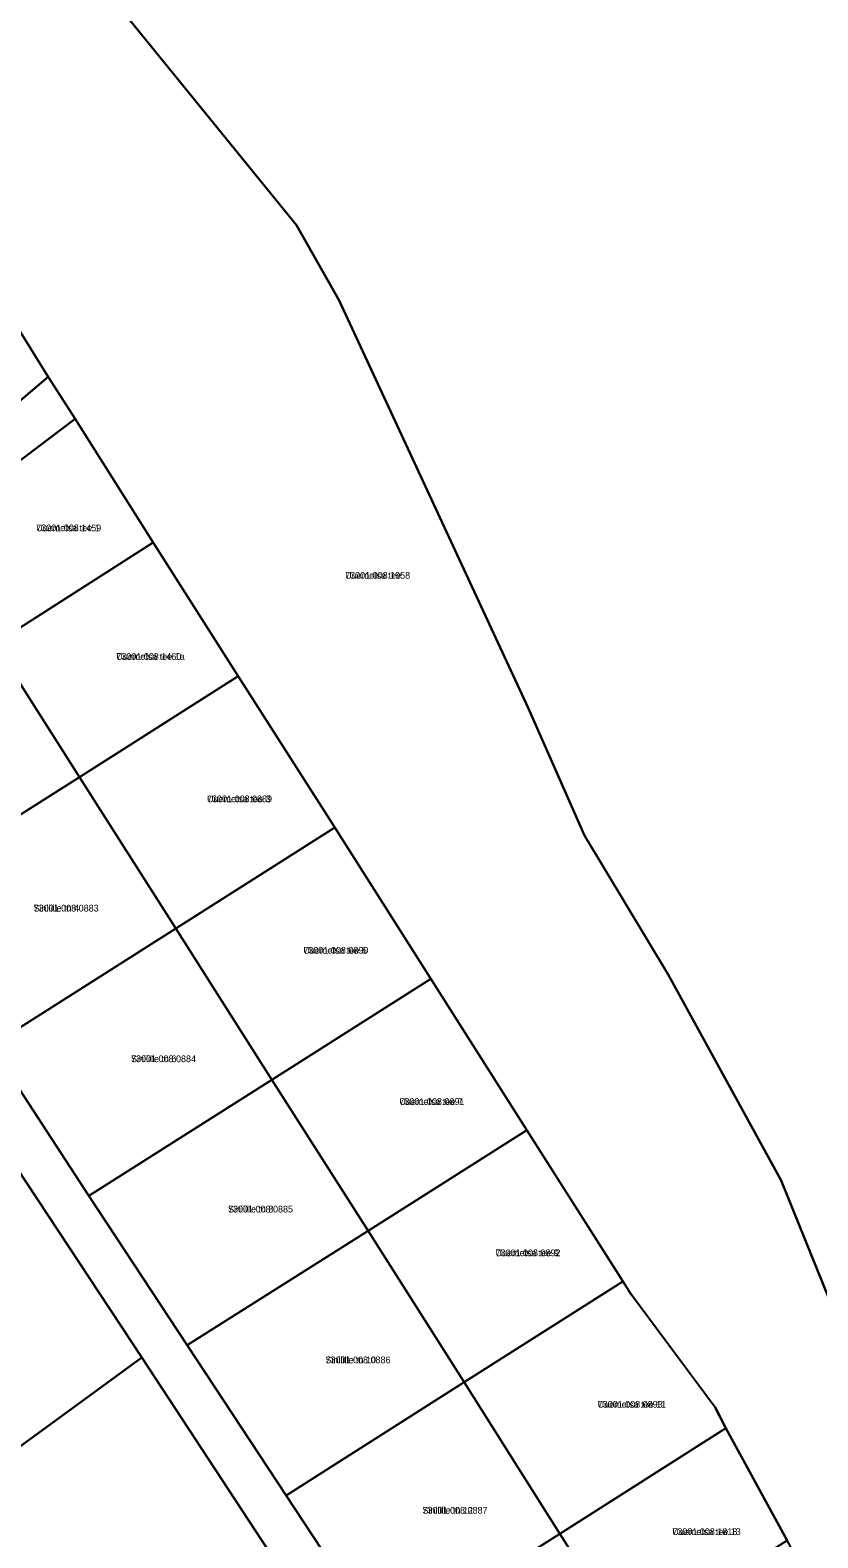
# Model space of a CAD drawing. Extents: x 524000 to 564260, y 6469338 to 6496391.
# Drawn here: x 533524.2 to 533700, y 6469655.2 to 6469991.7 of the extents above; entities that cross this region are included whole.
import ezdxf

# ---------------------------------------------------------------- set-up
doc = ezdxf.new("R2010")
doc.units = 0
for name, color, linetype in [('L_AADRESS', 7, 'Continuous'), ('PIIR', 7, 'Continuous'), ('TUNNUS', 7, 'Continuous')]:
    doc.layers.add(name, color=color, linetype=linetype)

msp = doc.modelspace()

# ---------------------------------------------------------------- linework, layer by layer
at = {"layer": 'PIIR'}
for points in [[(533707.29, 6469629.03), (533693.17, 6469654.63), (533679.45, 6469679.69), (533677.05, 6469684.35), (533658.36, 6469709.54), (533656.52, 6469712.46), (533635.06, 6469746.26), (533613.63, 6469780.01), (533592.22, 6469813.75), (533570.65, 6469847.58), (533551.7, 6469877.35), (533534.27, 6469905.02), (533528.24, 6469914.37), (533519.16, 6469929.05), (533512.73, 6469939.07), (533496, 6469965.43), (533477.73, 6469994.16), (533459.77, 6470022.41), (533441.78, 6470050.64), (533423.84, 6470078.86), (533406.93, 6470105.53), (533334.15, 6470219.84), (533366.74, 6470405.16)], [(533443.33, 6470281.42), (533455.72, 6470142.44), (533466.32, 6470106.55), (533484.5, 6470075.84), (533535.48, 6470007.6), (533583.67, 6469948.17), (533593.15, 6469931.4), (533635.38, 6469840.51), (533647.92, 6469811.97), (533666.59, 6469780.98), (533691.79, 6469735.01), (533706.46, 6469698.76)], [(533706.46, 6469698.76), (533691.79, 6469735.01), (533666.59, 6469780.98), (533647.92, 6469811.97), (533635.38, 6469840.51), (533593.15, 6469931.4), (533583.67, 6469948.17), (533535.48, 6470007.6), (533484.5, 6470075.84), (533466.32, 6470106.55), (533455.72, 6470142.44), (533443.33, 6470281.42)], [(533503.63, 6469893.48), (533528.24, 6469914.37), (533534.27, 6469905.02), (533500.56, 6469879.53)], [(533589.38, 6469634.14), (533549.14, 6469695.46), (533518.84, 6469741.37), (533483.62, 6469795.28), (533482.41, 6469796.94), (533479.09, 6469801.97), (533452.26, 6469843.09), (533428.19, 6469824.99), (533459.11, 6469777.85), (533429.89, 6469756.94), (533421.78, 6469751.12), (533397.38, 6469733.71), (533363.95, 6469709.79), (533356.8, 6469704.6), (533355.57, 6469703.73), (533320.24, 6469733.53), (533296.89, 6469711.44), (533265.52, 6469681.64), (533290.95, 6469647.29)], [(533515.41, 6469765.02), (533537.34, 6469731.56), (533559.25, 6469698.23), (533581.35, 6469664.68), (533603.28, 6469631.34)]]:
    msp.add_lwpolyline(points, dxfattribs=at)
for points in [[(533486.73, 6469922.5), (533512.75, 6469939.08), (533519.13, 6469929.04), (533528.24, 6469914.37), (533503.63, 6469893.48)], [(533534.27, 6469905.02), (533551.7, 6469877.35), (533516.26, 6469854.77), (533500.56, 6469879.53)], [(533460.2, 6469849.08), (533500.56, 6469879.53), (533535.2, 6469825.04), (533493.37, 6469798.5)], [(533551.7, 6469877.35), (533570.65, 6469847.58), (533535.2, 6469825.04), (533516.26, 6469854.77)], [(533535.2, 6469825.04), (533570.65, 6469847.58), (533592.19, 6469813.78), (533556.74, 6469791.26)], [(533493.37, 6469798.5), (533535.2, 6469825.04), (533556.74, 6469791.26), (533515.41, 6469765.02)], [(533556.74, 6469791.26), (533592.19, 6469813.78), (533613.63, 6469780.01), (533578.18, 6469757.49)], [(533515.41, 6469765.02), (533556.74, 6469791.26), (533578.18, 6469757.49), (533537.34, 6469731.56)], [(533578.18, 6469757.49), (533613.63, 6469780.01), (533635.07, 6469746.24), (533599.62, 6469723.73)], [(533537.34, 6469731.56), (533578.18, 6469757.49), (533599.62, 6469723.73), (533559.25, 6469698.23)], [(533599.62, 6469723.73), (533635.07, 6469746.24), (533656.51, 6469712.48), (533621.05, 6469689.97)], [(533469.94, 6469705.73), (533518.84, 6469741.37), (533549.14, 6469695.46), (533503.79, 6469662.4)], [(533559.25, 6469698.23), (533599.62, 6469723.73), (533621.05, 6469689.97), (533581.35, 6469664.68)], [(533656.51, 6469712.48), (533658.38, 6469709.53), (533677.07, 6469684.38), (533679.45, 6469679.69), (533642.42, 6469656.13), (533621.05, 6469689.97)], [(533549.14, 6469695.46), (533589.38, 6469634.14), (533546.52, 6469607.58), (533503.79, 6469662.4)], [(533581.35, 6469664.68), (533621.05, 6469689.97), (533642.42, 6469656.13), (533603.28, 6469631.34)], [(533642.42, 6469656.13), (533679.45, 6469679.69), (533693.17, 6469654.63), (533657.66, 6469632.08)], [(533597.64, 6469609.89), (533611.5, 6469618.71), (533603.28, 6469631.34), (533642.42, 6469656.13), (533657.66, 6469632.08), (533674.05, 6469606.47), (533628.4, 6469575.72)]]:
    msp.add_lwpolyline(points, close=True, dxfattribs=at)

# ---------------------------------------------------------------- texts
at = {"layer": 'L_AADRESS'}
for s, p in [('Uuemetsa tee 1', (533525.57, 6469879.9)), ('Uuemetsa tee', (533594.51, 6469869.31)), ('Uuemetsa tee 1a', (533543.44, 6469851.2)), ('Uuemetsa tee 3', (533563.69, 6469819.42)), ('Sinilille tn 4', (533525, 6469795.03)), ('Uuemetsa tee 5', (533585.19, 6469785.63)), ('Sinilille tn 6', (533546.73, 6469761.41)), ('Uuemetsa tee 7', (533606.62, 6469751.87)), ('Sinilille tn 8', (533568.38, 6469727.86)), ('Uuemetsa tee 9', (533628.06, 6469718.1)), ('Sinilille tn 10', (533590.13, 6469694.21)), ('Uuemetsa tee 11', (533650.87, 6469684.3)), ('Sinilille tn 12', (533611.78, 6469660.65)), ('Uuemetsa tee 13', (533667.53, 6469655.88))]:
    msp.add_text(s, height=1.5, dxfattribs=at).set_placement(p)
at = {"layer": 'TUNNUS'}
for s, p in [('73001:008:1459', (533525.57, 6469879.9)), ('73001:008:1958', (533594.51, 6469869.31)), ('73001:008:1460', (533543.44, 6469851.2)), ('73001:008:0889', (533563.69, 6469819.42)), ('73001:008:0883', (533525, 6469795.03)), ('73001:008:0890', (533585.19, 6469785.63)), ('73001:008:0884', (533546.73, 6469761.41)), ('73001:008:0891', (533606.62, 6469751.87)), ('73001:008:0885', (533568.38, 6469727.86)), ('73001:008:0892', (533628.06, 6469718.1)), ('73001:008:0886', (533590.13, 6469694.21)), ('73001:008:0893', (533650.87, 6469684.3)), ('73001:008:0887', (533611.78, 6469660.65)), ('73001:008:1818', (533667.53, 6469655.88))]:
    msp.add_text(s, height=1.5, dxfattribs=at).set_placement(p)

doc.saveas('drawing.dxf')
